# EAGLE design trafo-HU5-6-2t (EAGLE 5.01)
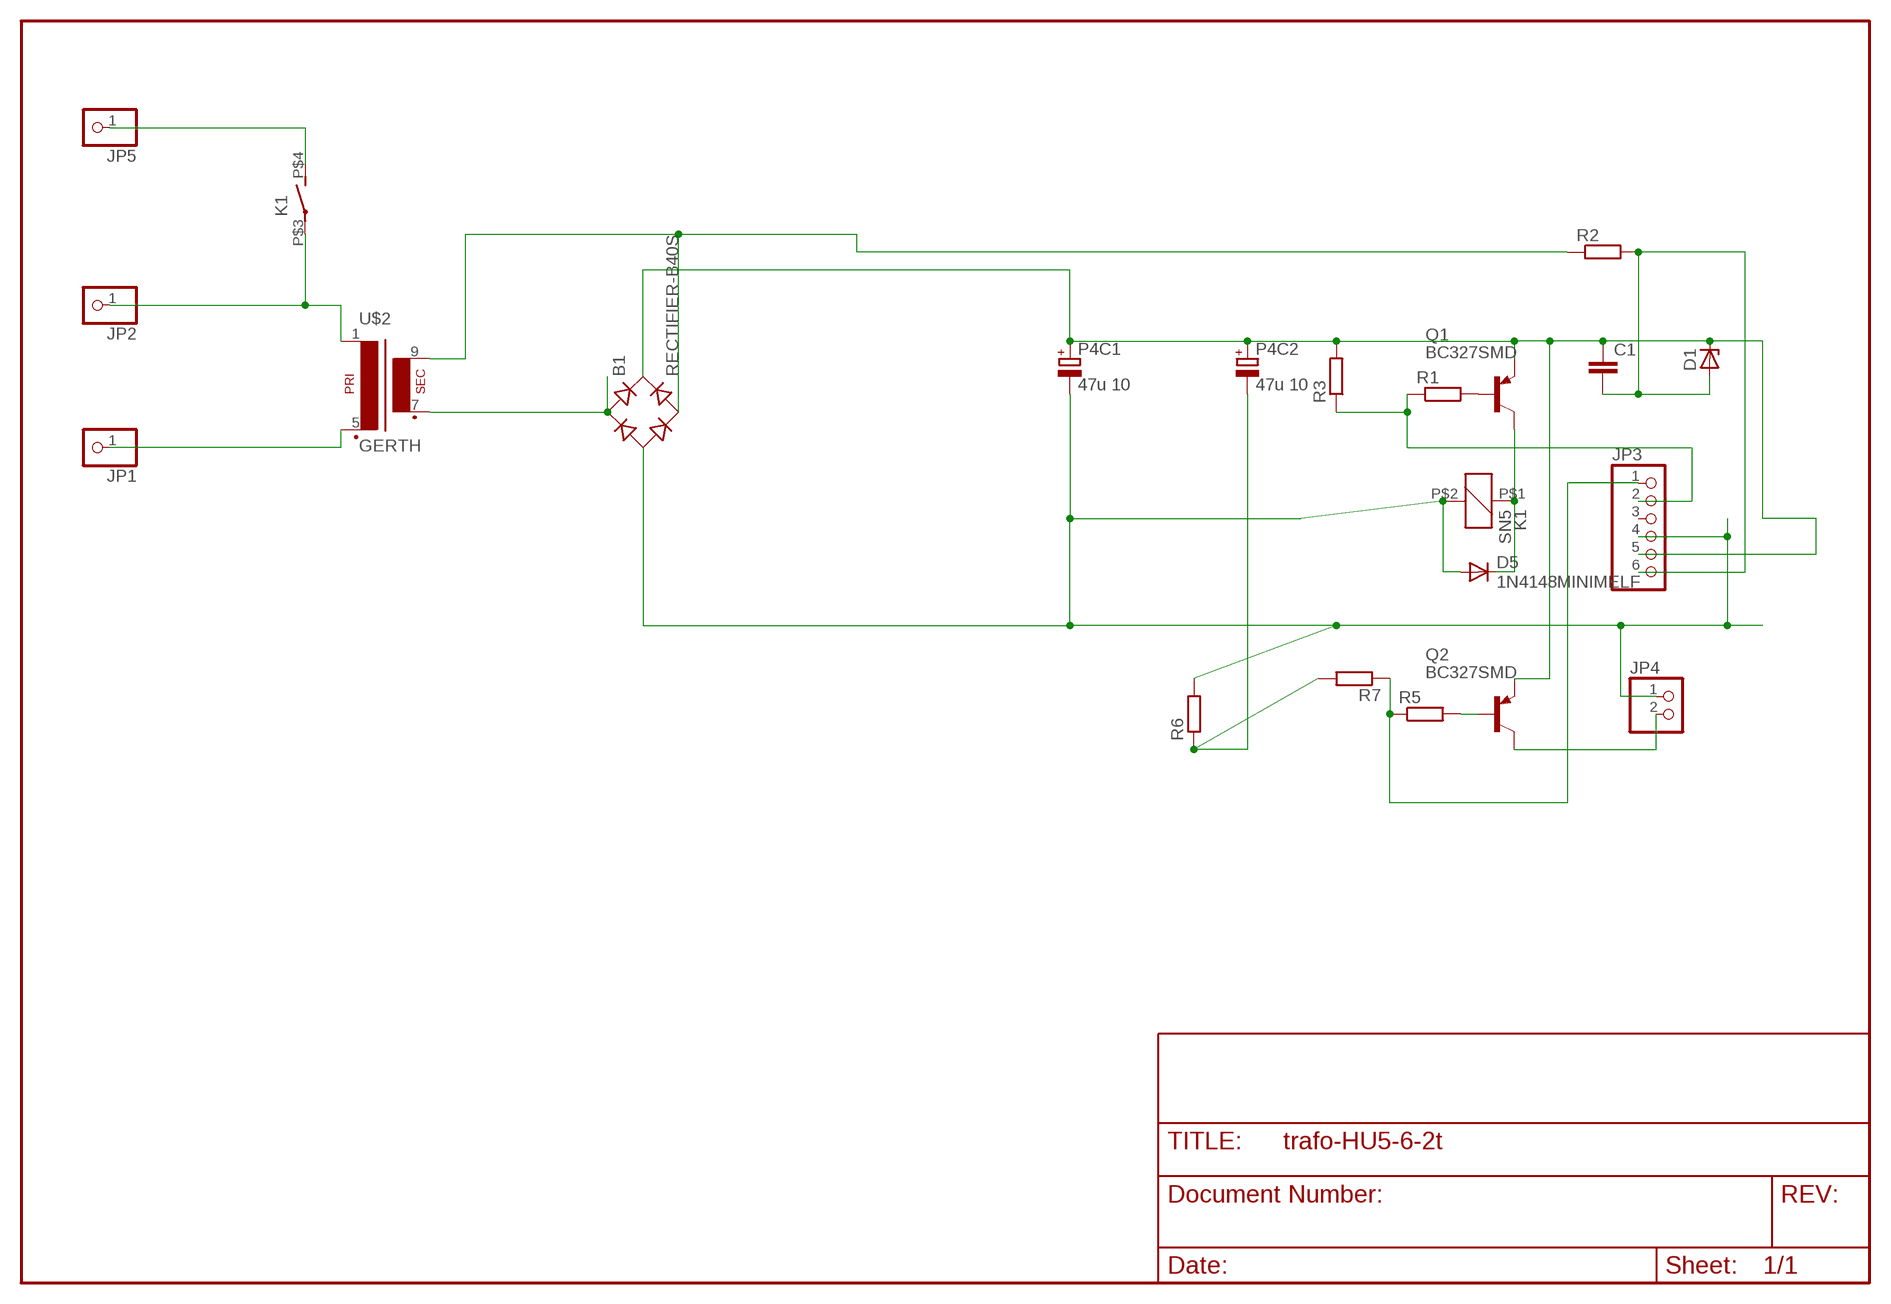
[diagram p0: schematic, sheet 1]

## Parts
B1  RECTIFIER-B40S  [B40S]
C1  C-EUC1206  [C1206]
D1  ZENER-DIODESOT23  [SOT23]
D5  1N4148MINIMELF  [MINIMELF]
JP1  PINHD-1X1  [1X01]
JP2  PINHD-1X1  [1X01]
JP3  PINHD-1X6  [1X06]
JP4  PINHD-1X2  [1X02]
JP5  PINHD-1X1  [1X01]
K1  SN5  [HU]
P4C1  47u 10  CPOL-EUE2-5  [E2-5]
P4C2  47u 10  CPOL-EUE2-5  [E2-5]
Q1  BC327SMD  [SOT23-BEC]
Q2  BC327SMD  [SOT23-BEC]
R1  R-EU_R0805  [R0805]
R2  R-EU_R0805  [R0805]
R3  R-EU_R0805  [R0805]
R5  R-EU_R1206  [R1206]
R6  R-EU_R0805  [R0805]
R7  R-EU_R0805  [R0805]
U$2  GERTH  [150.06]

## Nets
N$1: JP2.1 K1.P$3(2:P) U$2.1
N$2: B1.+ C1.1 D1.3(C) JP3.5 P4C1.+ P4C2.+ Q1.E Q2.E R3.2
N$3: B1.- D5.A JP3.4 JP4.1 K1.P$2 P4C1.- R6.2
N$4: JP5.1 K1.P$4(2:S)
N$5: JP1.1 U$2.5(P2)
N$6: B1.AC1 U$2.7(S3)
N$7: B1.AC2 R2.1 U$2.9(S4)
N$8: Q1.B R1.2
N$9: C1.2 D1.1(A) JP3.6 R2.2
N$10: JP3.2 R1.1 R3.1
N$11: D5.C K1.P$1 Q1.C
N$12: JP4.2 Q2.C
N$13: JP3.1 R5.1 R7.1
N$15: Q2.B R5.2
N$16: P4C2.- R6.1 R7.2
Unconnected: JP3.3

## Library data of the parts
B1 = rectifier:RECTIFIER-: Rectifier
C1 = rcl-2:C-EU: CAPACITOR, European symbol
D1 = diode-1:ZENER-DIODE: Z-Diode
D5 = diode-1:1N4148: DIODE
JP1 JP2 JP5 = pinhead(2):PINHD-1X1: PIN HEADER
JP3 = pinhead:PINHD-1X6: PIN HEADER
JP4 = pinhead:PINHD-1X2: PIN HEADER
K1 = relay:SN*: Slim PCB Relay 1 pole 6 A SCHRACK Source: http://www.schrack.com/.. 5815.pdf
P4C1 P4C2 = rcl:CPOL-EU: POLARIZED CAPACITOR, European symbol
Q1 Q2 = transistor-pnp:BC327*: PNP Transistror
R1-R3 R5-R7 = rcl-2:R-EU_: RESISTOR, European symbol
U$2 = trafo:GERTH

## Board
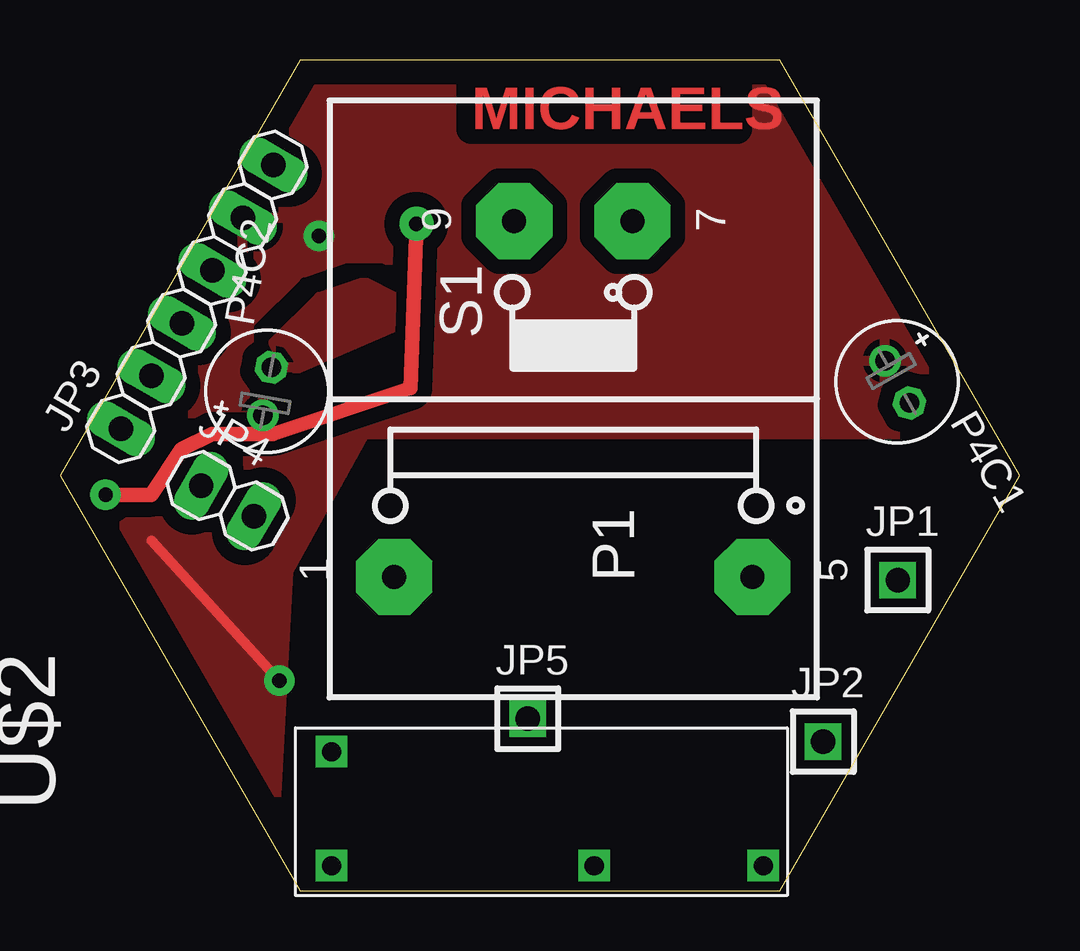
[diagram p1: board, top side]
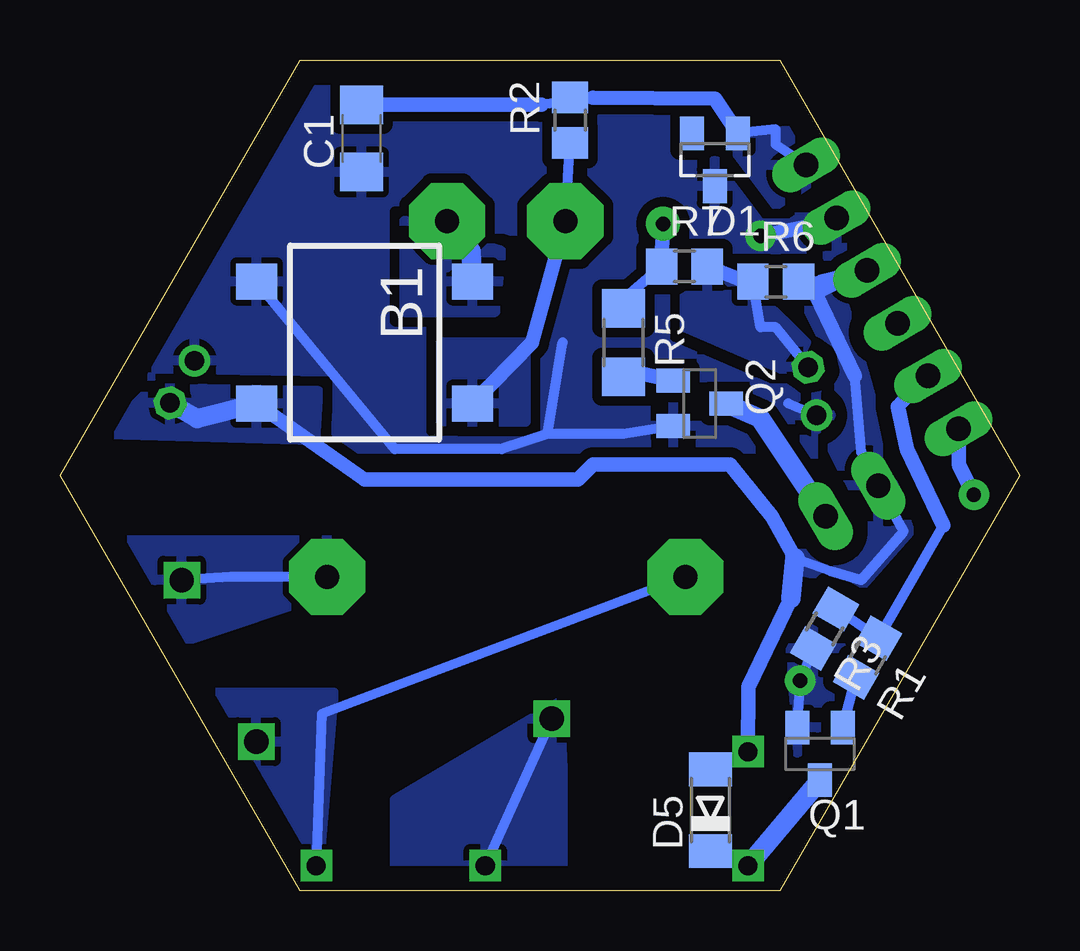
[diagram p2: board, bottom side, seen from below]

Size 40 x 34.64 mm. Coordinates in mm from the lower left corner, seen from the top.
Outline: 10,0 30,0 40,17.32 30,34.64 10,34.64 0,17.32 10,0
Copper layers (1*16): Top 0.035mm / dielectric 1.5mm / Bottom 0.035mm
Design rules "default": minimum track width 10mil, minimum drill 24mil, track to track 8mil, track to pad 8mil, pad to pad 8mil, via to via 8mil, smd to smd 8mil, copper to edge 40mil, drill to drill 8mil, minimum pad ring 10mil, minimum via ring 8mil, stop-mask expansion 4mil, vias tented up to drill 0mil, thermal gap 10mil

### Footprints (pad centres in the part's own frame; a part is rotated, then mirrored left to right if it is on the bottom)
B40S = smd 1.5 x 1.7: + -2.55,-4.5; - 2.55,-4.5; AC1 -2.55,4.5; AC2 2.55,4.5
C1206 = smd 1.6 x 1.8: 1 -1.4,0; 2 1.4,0
SOT23 = smd 1 x 1.4: 1 -0.95,-1.1; 2 0.95,-1.1; 3 0,1.1
MINIMELF = smd 1.4 x 1.8: A 1.7,0; C -1.7,0
1X01 = drill 1.016 square: 1 0,0
1X06 = drill 1.016 long: 1 -6.35,0; 2 -3.81,0; 3 -1.27,0; 4 1.27,0; 5 3.81,0; 6 6.35,0
1X02 = drill 1.016 long: 1 -1.27,0; 2 1.27,0
HU = drill 0.8 square: P$1 2.25,-9; P$2 -2.5,-9; P$3 2.25,9; P$4 2.25,1.95
E2-5 = drill 0.813 pad 1.27 round: + -1.016,0 | drill 0.813 pad 1.27 octagon: - 1.016,0
SOT23-BEC = smd 1 x 1.4: B -0.95,-1.1; C 0,1.1; E 0.95,-1.1
R0805 = smd 1.3 x 1.5: 1 -0.95,0; 2 0.95,0
R1206 = smd 1.6 x 1.803: 1 -1.422,0; 2 1.422,0
150.06 = drill 1 pad 3.175 octagon: 1 -7.417,7.468; 5 -7.417,-7.468; 7 7.417,-2.464; 9 7.417,2.464

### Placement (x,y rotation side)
B1  27.3,22.86 270 bottom
C1  27.43,31.37 90 bottom
D1  12.7,30.48 180 bottom
D5  12.89,3.37 90 bottom
JP1  34.92,12.95 0 top
JP2  31.81,6.22 0 top
JP3  5.71,24.77 60 top
JP4  6.99,16.26 330 top
JP5  19.49,7.18 0 top
K1  20.32,3.3 270 top
P4C1  34.9,21.22 300 top
P4C2  8.64,20.83 80 top
Q1  8.32,5.71 180 bottom
Q2  13.34,20.32 270 bottom
R1  6.34,9.71 240 bottom
R2  18.73,32.13 90 bottom
R3  8.13,10.92 240 bottom
R5  16.51,22.86 270 bottom
R6  10.16,25.4 0 bottom
R7  13.97,26.04 0 bottom
U$2  21.4,20.51 90 top

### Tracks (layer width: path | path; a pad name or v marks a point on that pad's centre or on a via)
N$1
  Bottom 0.406: U$2.1 29.09,7.38 K1.P$3
  pour Bottom (isolate 0.61, rank 2): 29.21,0.64 28.57,8.26 34.92,8.26
N$2  (via drill 0.6 pad 1.27)
  Top 0.406: v9.14,8.76 3.81,14.61
  Bottom 0.406: Q1.E v9.14,8.76 R3.2 | Q2.E 16.51,19.05 19.68,19.05 | 19.68,19.05 19.05,22.86 | B1.+ 26.04,18.41 21.59,18.41 19.68,19.05 | P4C2.+ 9.65,20.32
  Bottom 0.61: v10.79,27.3 7.62,27.94
  pour Top (isolate 0.61, rank 3): 0,15.24 8.89,1.27 9.53,13.34 12.7,19.05 38.1,19.05 29.21,33.66 10.79,33.66
  pour Bottom (isolate 0.406, rank 3): 0,15.24 8.89,1.27 10.16,18.41 38.1,18.41 29.21,33.66 10.79,33.66
N$3
  Bottom 0.406: D5.A K1.P$2 | 8.26,25.4 R6.2 | 6.35,26.04 JP3.4 | 9.37,13.88 7.87,13.34 6.6,12.95 4.83,14.99 JP4.1 6.6,18.29 6.86,21.46
  Bottom 0.61: B1.- 27.3,17.14 18.41,17.14 17.78,17.78 12.06,17.78 10.33,15.61 9.37,13.88 | K1.P$2 11.3,8.51 9.53,12.19 | JP3.4 8.26,25.4 | 6.86,21.46 8.51,24.89 6.35,26.04
  Bottom 0.813: B1.- 34.29,19.68 P4C1.- | 9.53,12.19 9.37,13.88
  pour Bottom (isolate 0.305): 29.21,20.83 36.2,20.95 38.1,19.05 29.34,18.8
  pour Bottom (isolate 0.61): 7.62,25.4 6.35,21.08 5.08,16.51 4.57,14.99 6.6,12.7 9.65,13.46 6.86,16.51 7.87,18.54 7.87,22.35 8.89,24.38
N$4
  Bottom 0.406: K1.P$4 JP5.1
  pour Bottom: 26.04,0.64 26.04,3.81 19.18,7.87 19.05,5.08 19.05,0.64
N$5
  Bottom 0.406: U$2.5 32.88,13.09 JP1.1
  pour Bottom (isolate 0.61, rank 2): 27.94,14.61 37.47,14.61 35.56,10.16 27.94,12.7
N$6
  Bottom 0.813: B1.AC1 22.86,26.67 U$2.7
  pour Bottom: 21.59,26.67 25.65,27.94 25.65,24.13 21.84,24.13
N$7
  Bottom 0.406: U$2.9 R2.1
  Bottom 0.61: U$2.9 20.32,22.86 B1.AC2
  pour Bottom: 20.57,22.86 24.13,22.86 24.13,19.56 20.57,19.56
N$8
  Bottom 0.406: Q1.B R1.2
N$9
  Bottom 0.406: D1.1 10.16,31.75 10.16,31.11 JP3.6 | R2.2 17.78,33.07 17.78,33.02 19.94,32.77
  Bottom 0.61: D1.1 12.7,33.02 17.78,33.07 | 19.94,32.77 C1.2
  pour Bottom (isolate 0.305): 8.26,29.84 9.53,31.75 12.06,31.11 10.16,28.57
N$10
  Bottom 0.406: R1.1 5.97,10.41 | R1.1 R3.1 | 3.94,21.46 JP3.2 | R1.1 3.17,15.24
  Bottom 0.61: 3.94,21.46 5.08,20.19 4.7,18.41 3.17,15.24
N$11
  Bottom 0.406: K1.P$1 D5.C
  Bottom 0.813: Q1.C K1.P$1
N$12
  Bottom 0.813: Q2.C 10.79,19.68 JP4.2
N$13  (via drill 0.6 pad 1.27, 0.6 pad 1.42)
  Top 0.61: v14.86,27.81 14.61,20.95 8.89,19.05 6.35,19.05 5.08,18.41 3.81,16.51 v1.91,16.51
  Bottom 0.406: R5.1 17.14,24.13 R7.1
  Bottom 0.61: JP3.1 2.54,17.78 v1.91,16.51 | v14.86,27.81 R7.1
N$15
  Bottom 0.406: 15.88,21.59 R5.2
  Bottom 0.61: Q2.B 15.88,21.59
N$16
  Bottom 0.406: R6.1 10.79,23.5 10.16,23.5 P4C2.-
  Bottom 0.61: R6.1 11.43,25.4 R7.2
  pour Bottom (isolate 0.406): 8.89,22.86 10.79,24.77 12.7,25.4 13.97,24.77 13.97,23.5 9.53,21.59
  pour Top (isolate 0.406): 8.89,22.86 10.79,24.77 12.7,25.4 13.97,24.77 13.97,23.5 9.53,21.59

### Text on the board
Top: MICHAELS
